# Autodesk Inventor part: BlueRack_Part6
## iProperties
Shininess: 64.0
Length Units: 11272
Angle Units: 11279
Time Units: 11290
Mass Units: 11286
Length Display Precision: 3
Angle Display Precision: 2
Compacted: True
Part Number: BlueRack_Part6
Document SubType Name: Modeling
Created: 2004-12
Designer: John Blackburn
Manufacturer: Standard
Standards Organization: Custom
Material: Steel, Mild
Density: 0.0
Volumn: 0.0
Area: 0.0
PropertySet Name: Model Information
Control State: 0
Master: False
Checked Out: False
Author: John Blackburn
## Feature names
1. Extrusion1
2. Extrusion3
